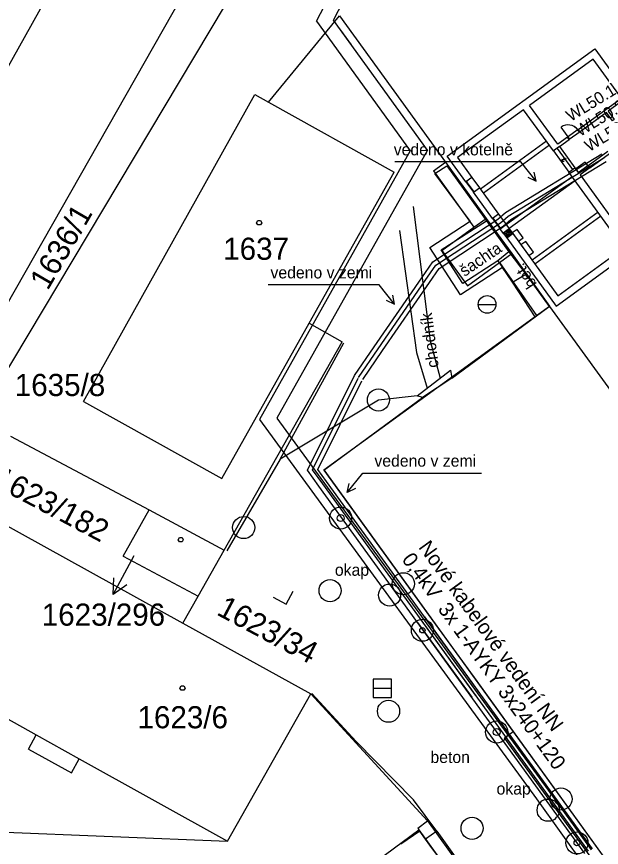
# Model space of a CAD drawing. Extents: x -762592 to -762444, y -1032635 to -1032425.
# Drawn here: x -762533.5 to -762493.8, y -1032606 to -1032549.7 of the extents above; entities that cross this region are included whole.
import ezdxf

# ---------------------------------------------------------------- set-up
doc = ezdxf.new("R2010")
doc.units = 0
for name, color, linetype in [('Chráničky - koruflex', 7, 'Continuous'), ('Kabeláž - kabelové vedení NN - nové', 7, 'Continuous'), ('Katastr - energomost - stávající', 7, 'Continuous'), ('Katastr - hranice parcel', 7, 'Continuous'), ('Katastr - komunikace a ostatní povrchy', 7, 'Continuous'), ('Katastr - nezapsaný geometr_ plán + parcelní čísla', 7, 'Continuous'), ('Katastr - oploceni_budovy aj', 7, 'Continuous'), ('Katastr - parcelní čísla - dotčená stavbou', 7, 'Continuous'), ('Katastr - parcelní čísla - nedotčené ostatní', 7, 'Continuous'), ('Katastr - vjezdy na pozemek', 7, 'Continuous'), ('Katastr - vnitřní kresba', 7, 'Continuous'), ('Popisky', 7, 'Continuous'), ('Popisky - stávající kabelové vedení', 7, 'Continuous')]:
    doc.layers.add(name, color=color, linetype=linetype)

msp = doc.modelspace()

# ---------------------------------------------------------------- linework, layer by layer
at = {"layer": 'Chráničky - koruflex'}
for p, q in [((-762505.806, -1032590.384), (-762502.071, -1032595.541)), ((-762506.269, -1032590.767), (-762502.604, -1032595.828)), ((-762502.338, -1032595.683), (-762506.042, -1032590.569))]:
    msp.add_line(p, q, dxfattribs=at)
at = {"layer": 'Kabeláž - kabelové vedení NN - nové'}
for p, q in [((-762500.303, -1032562.966), (-762493.776, -1032558.987)), ((-762500.127, -1032563.21), (-762493.643, -1032559.258)), ((-762499.95, -1032563.453), (-762493.488, -1032559.515)), ((-762505.244, -1032566.322), (-762500.84, -1032563.422)), ((-762500.84, -1032563.422), (-762500.303, -1032562.966)), ((-762500.659, -1032563.662), (-762500.127, -1032563.21)), ((-762500.479, -1032563.903), (-762499.95, -1032563.453)), ((-762505.03, -1032566.54), (-762500.659, -1032563.662)), ((-762504.816, -1032566.759), (-762500.479, -1032563.903)), ((-762505.987, -1032567.401), (-762505.244, -1032566.322)), ((-762505.751, -1032567.588), (-762505.03, -1032566.54)), ((-762505.475, -1032567.715), (-762504.816, -1032566.759)), ((-762509.21, -1032572.083), (-762505.987, -1032567.401)), ((-762508.939, -1032572.218), (-762505.751, -1032567.588)), ((-762508.655, -1032572.335), (-762505.475, -1032567.715)), ((-762510.545, -1032574.021), (-762509.21, -1032572.083)), ((-762510.271, -1032574.152), (-762508.939, -1032572.218)), ((-762509.996, -1032574.283), (-762508.655, -1032572.335)), ((-762513.745, -1032580.445), (-762510.545, -1032574.021)), ((-762513.046, -1032580.388), (-762510.05, -1032574.374)), ((-762512.967, -1032581.519), (-762513.745, -1032580.445)), ((-762512.456, -1032581.202), (-762513.046, -1032580.388)), ((-762494.415, -1032606.112), (-762512.456, -1032581.202)), ((-762494.929, -1032606.425), (-762512.967, -1032581.519))]:
    msp.add_line(p, q, dxfattribs=at)
for points in [[(-762513.395, -1032580.417), (-762510.297, -1032574.198)], [(-762512.705, -1032581.369), (-762513.395, -1032580.417)], [(-762494.683, -1032606.253), (-762512.705, -1032581.369)]]:
    msp.add_lwpolyline(points, dxfattribs=at)
at = {"layer": 'Katastr - energomost - stávající'}
for p, q in [((-762513.136, -1032550), (-762506.559, -1032537.258)), ((-762505.592, -1032558.74), (-762511.975, -1032549.93)), ((-762513.136, -1032550), (-762506.768, -1032558.79)), ((-762510.754, -1032551.614), (-762511.488, -1032550.601)), ((-762506.768, -1032558.79), (-762517.005, -1032576.99)), ((-762505.592, -1032558.74), (-762515.818, -1032576.919)), ((-762515.818, -1032576.919), (-762497.41, -1032602.131)), ((-762517.005, -1032576.99), (-762498.22, -1032602.717)), ((-762497.41, -1032602.131), (-762494.495, -1032606.178)), ((-762498.22, -1032602.717), (-762488.357, -1032616.413))]:
    msp.add_line(p, q, dxfattribs=at)
msp.add_lwpolyline([(-762511.975, -1032549.93), (-762505.687, -1032537.748)], dxfattribs=at)
for centre, radius in [((-762511.497, -1032583.685), 0.236), ((-762505.947, -1032591.286), 0.18), ((-762500.908, -1032598.184), 0.235), ((-762495.468, -1032605.698), 0.196)]:
    msp.add_circle(centre, radius, dxfattribs=at)
at = {"layer": 'Katastr - hranice parcel'}
for p, q in [((-762554.188, -1032589.048), (-762527.19, -1032540.86)), ((-762543.41, -1032585.51), (-762521.44, -1032546.89)), ((-762536.08, -1032576.94), (-762519.3, -1032548.89)), ((-762516.38, -1032555.5), (-762511.56, -1032549.65)), ((-762511.56, -1032549.65), (-762504.38, -1032559.56)), ((-762516.38, -1032555.5), (-762507.87, -1032560.24)), ((-762505.2, -1032560.14), (-762504.38, -1032559.56)), ((-762513.63, -1032570.48), (-762507.87, -1032560.24)), ((-762505.2, -1032560.14), (-762502.45, -1032563.97)), ((-762504.63, -1032565.55), (-762502.45, -1032563.97)), ((-762504.63, -1032565.55), (-762502.9, -1032567.94)), ((-762502.9, -1032567.94), (-762500.72, -1032566.36)), ((-762500.72, -1032566.36), (-762498.21, -1032569.96)), ((-762512.63, -1032580.41), (-762498.21, -1032569.96)), ((-762513.63, -1032570.48), (-762511.38, -1032571.73)), ((-762519.38, -1032585.85), (-762511.38, -1032571.73)), ((-762533.87, -1032578.12), (-762524.47, -1032583.13)), ((-762512.63, -1032580.41), (-762479.64, -1032626.03)), ((-762536.41, -1032582.94), (-762522.19, -1032590.8)), ((-762526.25, -1032586.26), (-762524.47, -1032583.13)), ((-762524.47, -1032583.13), (-762519.38, -1032585.85)), ((-762521.16, -1032588.98), (-762519.38, -1032585.85)), ((-762526.25, -1032586.26), (-762521.16, -1032588.98)), ((-762522.19, -1032590.8), (-762521.16, -1032588.98)), ((-762522.19, -1032590.8), (-762513.52, -1032595.6)), ((-762519.17, -1032605.59), (-762513.52, -1032595.6)), ((-762513.52, -1032595.6), (-762505.6, -1032604.21)), ((-762506.26, -1032604.69), (-762505.6, -1032604.21)), ((-762505.6, -1032604.21), (-762499.9, -1032612.12)), ((-762535.19, -1032604.93), (-762519.17, -1032605.59)), ((-762510.09, -1032607.68), (-762506.18, -1032604.81)), ((-762506.26, -1032604.69), (-762506.18, -1032604.81))]:
    msp.add_line(p, q, dxfattribs=at)
at = {"layer": 'Katastr - komunikace a ostatní povrchy'}
for p, q in [((-762502.158, -1032569.2), (-762500.958, -1032569.2)), ((-762509.294, -1032595.22), (-762508.044, -1032595.22))]:
    msp.add_line(p, q, dxfattribs=at)
for points in [[(-762502.698, -1032563.568), (-762505.099, -1032560.324), (-762504.295, -1032559.801), (-762500.088, -1032565.636), (-762498.928, -1032567.145)], [(-762506.575, -1032562.565), (-762505.431, -1032571.662), (-762504.734, -1032574.191)], [(-762500.512, -1032566.708), (-762503.373, -1032568.553), (-762505.444, -1032565.341), (-762502.698, -1032563.568)], [(-762500.831, -1032566.252), (-762503.206, -1032567.779), (-762504.67, -1032565.508), (-762501.607, -1032563.53)], [(-762507.494, -1032564.2), (-762506.354, -1032572.449), (-762505.628, -1032574.877)], [(-762500.088, -1032565.636), (-762500.831, -1032566.252), (-762500.512, -1032566.708)], [(-762499.837, -1032567.698), (-762500.512, -1032566.708)], [(-762498.302, -1032570.044), (-762499.837, -1032567.698), (-762498.928, -1032567.145), (-762497.34, -1032569.344)], [(-762506.311, -1032575.401), (-762504.039, -1032573.657), (-762503.94, -1032574.189), (-762505.946, -1032575.505), (-762506.311, -1032575.401)], [(-762506.311, -1032575.401), (-762508.927, -1032575.681), (-762515.585, -1032579.684)], [(-762490.357, -1032612.409), (-762500.383, -1032598.573), (-762499.795, -1032598.143)], [(-762504.974, -1032604.914), (-762505.736, -1032605.456)], [(-762504.974, -1032604.914), (-762499.854, -1032612.035)]]:
    msp.add_lwpolyline(points, dxfattribs=at)
msp.add_lwpolyline([(-762509.294, -1032595.847), (-762508.043, -1032595.847), (-762508.043, -1032594.593), (-762509.294, -1032594.593)], close=True, dxfattribs=at)
for centre, radius in [((-762501.558, -1032569.2), 0.6), ((-762508.927, -1032575.681), 0.75), ((-762511.497, -1032583.685), 0.75), ((-762518.065, -1032584.323), 0.75), ((-762507.24, -1032588.137), 0.75), ((-762512.207, -1032588.6), 0.75), ((-762508.173, -1032588.902), 0.75), ((-762505.947, -1032591.286), 0.75), ((-762508.246, -1032596.774), 0.75), ((-762500.908, -1032598.184), 0.75), ((-762496.55, -1032602.725), 0.75), ((-762497.418, -1032603.48), 0.75), ((-762502.579, -1032604.708), 0.75), ((-762495.468, -1032605.698), 0.75)]:
    msp.add_circle(centre, radius, dxfattribs=at)
at = {"layer": 'Katastr - nezapsaný geometr_ plán + parcelní čísla'}
for p, q in [((-762499.904, -1032564.456), (-762500.463, -1032564.368)), ((-762499.94, -1032564.483), (-762500.437, -1032564.404)), ((-762499.831, -1032564.404), (-762500.39, -1032564.315)), ((-762500.013, -1032564.536), (-762500.384, -1032564.477)), ((-762500.049, -1032564.562), (-762500.358, -1032564.513)), ((-762499.844, -1032564.37), (-762500.354, -1032564.289)), ((-762500.122, -1032564.615), (-762500.305, -1032564.586)), ((-762499.897, -1032564.297), (-762500.281, -1032564.236)), ((-762499.923, -1032564.261), (-762500.245, -1032564.21)), ((-762499.976, -1032564.188), (-762500.172, -1032564.157)), ((-762500.002, -1032564.152), (-762500.136, -1032564.13)), ((-762500.055, -1032564.079), (-762500.063, -1032564.078)), ((-762500.158, -1032564.641), (-762500.279, -1032564.622))]:
    msp.add_line(p, q, dxfattribs=at)
for points in [[(-762496.65, -1032558.507), (-762497.054, -1032558.801), (-762499.088, -1032556.002), (-762503.562, -1032559.252), (-762502.586, -1032560.595), (-762502.991, -1032560.889), (-762504.26, -1032559.142), (-762494.261, -1032551.877)], [(-762494.261, -1032551.877), (-762488.107, -1032560.347)], [(-762488.511, -1032560.641), (-762489.628, -1032559.104), (-762489.547, -1032559.045), (-762492.257, -1032555.316), (-762493.349, -1032556.109), (-762492.937, -1032556.675), (-762493.059, -1032556.764), (-762493.47, -1032556.197), (-762495.258, -1032557.496), (-762495.376, -1032557.335), (-762492.455, -1032555.213), (-762494.371, -1032552.575), (-762498.683, -1032555.708)], [(-762496.65, -1032558.507), (-762496.65, -1032558.507), (-762495.986, -1032558.025), (-762496.104, -1032557.864), (-762496.767, -1032558.346), (-762498.683, -1032555.708)], [(-762495.946, -1032557.996), (-762496.534, -1032557.187)], [(-762495.376, -1032557.335), (-762496.104, -1032557.864)], [(-762495.258, -1032557.496), (-762495.986, -1032558.025)], [(-762495.299, -1032557.526), (-762495.416, -1032557.364)], [(-762497.533, -1032558.142), (-762502.007, -1032561.392)], [(-762497.339, -1032558.409), (-762501.813, -1032561.659)], [(-762497.054, -1032558.801), (-762496.014, -1032560.233)], [(-762496.811, -1032558.625), (-762495.771, -1032560.057)], [(-762496.65, -1032558.507), (-762495.609, -1032559.939)], [(-762494.711, -1032559.781), (-762493.368, -1032558.805)], [(-762496.534, -1032559.517), (-762496.454, -1032559.334)], [(-762496.291, -1032559.341), (-762496.534, -1032559.517)], [(-762496.534, -1032559.517), (-762496.335, -1032559.497)], [(-762494.593, -1032559.943), (-762493.25, -1032558.967)], [(-762500.228, -1032564.692), (-762499.823, -1032564.398), (-762496.761, -1032568.613), (-762492.287, -1032565.362), (-762496.014, -1032560.233), (-762495.609, -1032559.939), (-762495.374, -1032560.263), (-762494.711, -1032559.781), (-762494.593, -1032559.943), (-762495.257, -1032560.425), (-762491.883, -1032565.068), (-762489.876, -1032563.611), (-762490.023, -1032563.409)], [(-762502.586, -1032560.595), (-762502.069, -1032561.307)], [(-762495.785, -1032560.549), (-762500.258, -1032563.799)], [(-762502.433, -1032561.572), (-762502.95, -1032560.86), (-762502.921, -1032560.9), (-762502.961, -1032560.93), (-762502.991, -1032560.889), (-762502.473, -1032561.601), (-762502.503, -1032561.561), (-762502.462, -1032561.531), (-762502.433, -1032561.572)], [(-762495.591, -1032560.816), (-762500.064, -1032564.066)], [(-762502.473, -1032561.601), (-762502.069, -1032561.307), (-762500.782, -1032563.079), (-762501.186, -1032563.373), (-762502.473, -1032561.601)], [(-762500.228, -1032564.692), (-762496.872, -1032569.311), (-762486.872, -1032562.046)], [(-762500.628, -1032564.056), (-762501.146, -1032563.344), (-762501.116, -1032563.384), (-762501.157, -1032563.413), (-762501.186, -1032563.373), (-762500.669, -1032564.085), (-762500.698, -1032564.045), (-762500.658, -1032564.015), (-762500.628, -1032564.056)], [(-762500.782, -1032563.079), (-762500.264, -1032563.791)], [(-762494.036, -1032562.956), (-762498.51, -1032566.206)], [(-762493.842, -1032563.223), (-762498.316, -1032566.473)], [(-762500.669, -1032564.085), (-762500.264, -1032563.791), (-762500.059, -1032564.074), (-762500.463, -1032564.368), (-762500.669, -1032564.085)], [(-762500.463, -1032564.368), (-762500.228, -1032564.692)], [(-762500.059, -1032564.074), (-762499.823, -1032564.398)]]:
    msp.add_lwpolyline(points, dxfattribs=at)
for points in [[(-762494.727, -1032559.793), (-762494.903, -1032559.55), (-762495.551, -1032560.02), (-762495.374, -1032560.263)], [(-762499.118, -1032564.689), (-762499.529, -1032564.122), (-762499.853, -1032564.357), (-762499.441, -1032564.924)], [(-762498.412, -1032565.659), (-762498.941, -1032564.931), (-762499.265, -1032565.166), (-762498.736, -1032565.895)]]:
    msp.add_lwpolyline(points, close=True, dxfattribs=at)
msp.add_circle((-762496.291, -1032559.341), 0.06, dxfattribs=at)
msp.add_arc((-762496.063, -1032557.834), 0.8, 36, 126, dxfattribs=at)
at = {"layer": 'Katastr - oploceni_budovy aj'}
for p, q in [((-762512.636, -1032580.444), (-762505.064, -1032590.899)), ((-762502.258, -1032594.737), (-762489.239, -1032612.742))]:
    msp.add_line(p, q, dxfattribs=at)
for points in [[(-762503.94, -1032574.189), (-762498.302, -1032570.044), (-762497.34, -1032569.344)], [(-762497.33, -1032569.337), (-762465.044, -1032613.788)], [(-762515.585, -1032579.684), (-762511.284, -1032571.812)], [(-762512.636, -1032580.444), (-762505.946, -1032575.505)], [(-762515.585, -1032579.684), (-762519.219, -1032585.901)], [(-762506.542, -1032602.776), (-762510.441, -1032598.829), (-762513.439, -1032595.565)], [(-762505.433, -1032605.86), (-762505.736, -1032605.456), (-762506.13, -1032604.896), (-762507.408, -1032605.795)]]:
    msp.add_lwpolyline(points, dxfattribs=at)
at = {"layer": 'Katastr - parcelní čísla - nedotčené ostatní'}
msp.add_line((-762526.912, -1032588.852), (-762525.486, -1032586.214), dxfattribs=at)
for points in [[(-762516.927, -1032563.516), (-762516.837, -1032563.666), (-762516.927, -1032563.816), (-762517.107, -1032563.816), (-762517.197, -1032563.666), (-762517.107, -1032563.516)], [(-762522.25, -1032585), (-762522.16, -1032585.15), (-762522.25, -1032585.3), (-762522.43, -1032585.3), (-762522.52, -1032585.15), (-762522.43, -1032585)], [(-762522.133, -1032595.058), (-762522.043, -1032595.208), (-762522.133, -1032595.358), (-762522.313, -1032595.358), (-762522.403, -1032595.208), (-762522.313, -1032595.058)]]:
    msp.add_lwpolyline(points, close=True, dxfattribs=at)
for points in [[(-762525.997, -1032588.211), (-762526.912, -1032588.852), (-762526.877, -1032587.735)], [(-762516.068, -1032589.046), (-762515.185, -1032589.516), (-762514.716, -1032588.633)]]:
    msp.add_lwpolyline(points, dxfattribs=at)
at = {"layer": 'Katastr - vjezdy na pozemek'}
for p, q in [((-762505.064, -1032590.899), (-762502.258, -1032594.737)), ((-762504.974, -1032604.914), (-762506.542, -1032602.776))]:
    msp.add_line(p, q, dxfattribs=at)
msp.add_lwpolyline([(-762504.341, -1032607.352), (-762505.433, -1032605.86)], dxfattribs=at)
at = {"layer": 'Katastr - vnitřní kresba'}
for p, q in [((-762528.93, -1032575.79), (-762517.32, -1032554.97)), ((-762517.32, -1032554.97), (-762516.38, -1032555.5)), ((-762504.38, -1032559.56), (-762501.62, -1032563.37)), ((-762502.45, -1032563.97), (-762501.62, -1032563.37)), ((-762501.62, -1032563.37), (-762499.89, -1032565.76)), ((-762500.72, -1032566.36), (-762499.89, -1032565.76)), ((-762499.89, -1032565.76), (-762497.32, -1032569.31)), ((-762498.21, -1032569.96), (-762497.32, -1032569.31)), ((-762519.56, -1032581.01), (-762513.63, -1032570.48)), ((-762528.93, -1032575.79), (-762519.56, -1032581.01)), ((-762541.92, -1032592.93), (-762532.13, -1032598.38)), ((-762532.66, -1032599.34), (-762532.13, -1032598.38)), ((-762532.13, -1032598.38), (-762529.22, -1032600)), ((-762532.66, -1032599.34), (-762529.75, -1032600.96)), ((-762529.75, -1032600.96), (-762529.22, -1032600)), ((-762529.22, -1032600), (-762519.17, -1032605.59)), ((-762506.18, -1032604.81), (-762500.57, -1032612.61))]:
    msp.add_line(p, q, dxfattribs=at)
at = {"layer": 'Popisky'}
for p, q in [((-762499.28, -1032559.527), (-762507.826, -1032559.527)), ((-762498.232, -1032560.849), (-762499.28, -1032559.527)), ((-762508.881, -1032567.867), (-762516.402, -1032567.867)), ((-762507.833, -1032569.189), (-762508.881, -1032567.867)), ((-762511.046, -1032581.95), (-762509.998, -1032580.628)), ((-762509.998, -1032580.628), (-762501.947, -1032580.628))]:
    msp.add_line(p, q, dxfattribs=at)
for points in [[(-762498.802, -1032560.583), (-762498.232, -1032560.849), (-762498.361, -1032560.234)], [(-762508.403, -1032568.923), (-762507.833, -1032569.189), (-762507.962, -1032568.573)], [(-762510.476, -1032581.684), (-762511.046, -1032581.95), (-762510.917, -1032581.335)]]:
    msp.add_lwpolyline(points, dxfattribs=at)

# ---------------------------------------------------------------- texts
at = {"layer": 'Katastr - parcelní čísla - dotčená stavbou'}
msp.add_text('1623/34', height=1.5, rotation=332, dxfattribs=at).set_placement((-762519.973, -1032590.199))
at = {"layer": 'Katastr - parcelní čísla - nedotčené ostatní'}
for s, rotation, p in [('1636/1', 59.8114, (-762531.357, -1032568.307)), ('1623/182', 332.1436, (-762535.13, -1032581.446))]:
    msp.add_text(s, height=1.5, rotation=rotation, dxfattribs=at).set_placement(p)
for s, p in [('1637', (-762519.455, -1032566.176)), ('1635/8', (-762533.591, -1032575.411)), ('1623/296', (-762531.76, -1032590.976)), ('1623/6', (-762525.268, -1032597.931))]:
    msp.add_text(s, height=1.5, dxfattribs=at).set_placement(p)
at = {"layer": 'Popisky'}
for s, p in [('vedeno v kotelně', (-762507.891, -1032559.098)), ('vedeno v zemi', (-762516.249, -1032567.437)), ('vedeno v zemi', (-762509.202, -1032580.198)), ('okap', (-762511.881, -1032587.594)), ('beton', (-762505.402, -1032600.282)), ('okap', (-762500.919, -1032602.421))]:
    msp.add_text(s, height=0.8, dxfattribs=at).set_placement(p)
for s, rotation, p in [('šachta', 34, (-762503.094, -1032567.347)), ('bet.', 123.1969, (-762498.155, -1032567.811)), ('chodník', 97.1676, (-762504.836, -1032573.447))]:
    msp.add_text(s, height=0.8, rotation=rotation, dxfattribs=at).set_placement(p)
at = {"layer": 'Popisky - stávající kabelové vedení'}
for s, height, rotation, p in [('WL50.1', 0.8, 31.5, (-762495.886, -1032556.835)), ('WL50.2', 0.8, 31.5, (-762495.259, -1032557.858)), ('WL50.3', 0.8, 31.5, (-762494.632, -1032558.881)), ('Nové kabelové vedení NN ', 1, 306, (-762506.252, -1032585.669)), ('0,4kV  3x 1-AYKY 3x240+120', 1, 306, (-762507.385, -1032586.492))]:
    msp.add_text(s, height=height, rotation=rotation, dxfattribs=at).set_placement(p)

doc.saveas('drawing.dxf')
